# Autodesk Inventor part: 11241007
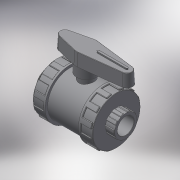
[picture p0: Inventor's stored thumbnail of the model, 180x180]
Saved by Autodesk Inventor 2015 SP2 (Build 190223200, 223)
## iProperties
Created: 2017-11
Part Number: 11241007
Material: Generic
Description: PLASSON BI STOP VALVE THR PVC 3/4"
Document SubType Name: Modeling
Designer: KIM
Density: 1 g/cm^3
Appearance: Default
Author: KIM
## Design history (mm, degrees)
derived "112410 - 112710.ipt"
feature "Solid1::112410 - 112710.ipt"
tag "TaggingFeature1"
body "Solid1"
other parameters: "d0" = 89, "d1" = 24.117, "d2" = 55, "d3" = 16, "d4" = 19.2936, "d5" = 11.2, "d7" = 33.7638, "d8" = 49.5, "d13" = 0.72351, "d23" = 16, "d24" = 52.8, "d25" = 0.48234, "d26" = 0.72351, "d27" = 8.25, "d28" = 4.125, "d29" = 12, "d30" = 0, "d35" = 0.72351, "d39" = 27.5, "d45" = 360 deg, "d47" = 0.48234, "d50" = 30.25, "d51" = 16.5, "d53" = 0, "d55" = 4.8234, "d56" = 2.4117, "d57" = 11.2, "d58" = 0, "d59" = 0.72351, "d61" = 360 deg, "d63" = 22, "d64" = 54, "d66" = 73, "d68" = 11, "d69" = 21.9, "d70" = 13.5, "d71" = 3 deg, "d73" = 1.1, "d74" = 29.2, "d75" = 1.62, "d76" = 0, "d77" = 0.48234, "G_" = 24.117, "l_" = 16, "H_" = 89, "K_" = 55, "F_" = 54, "J_" = 73, "d67" = 22, "d72" = 5.5
